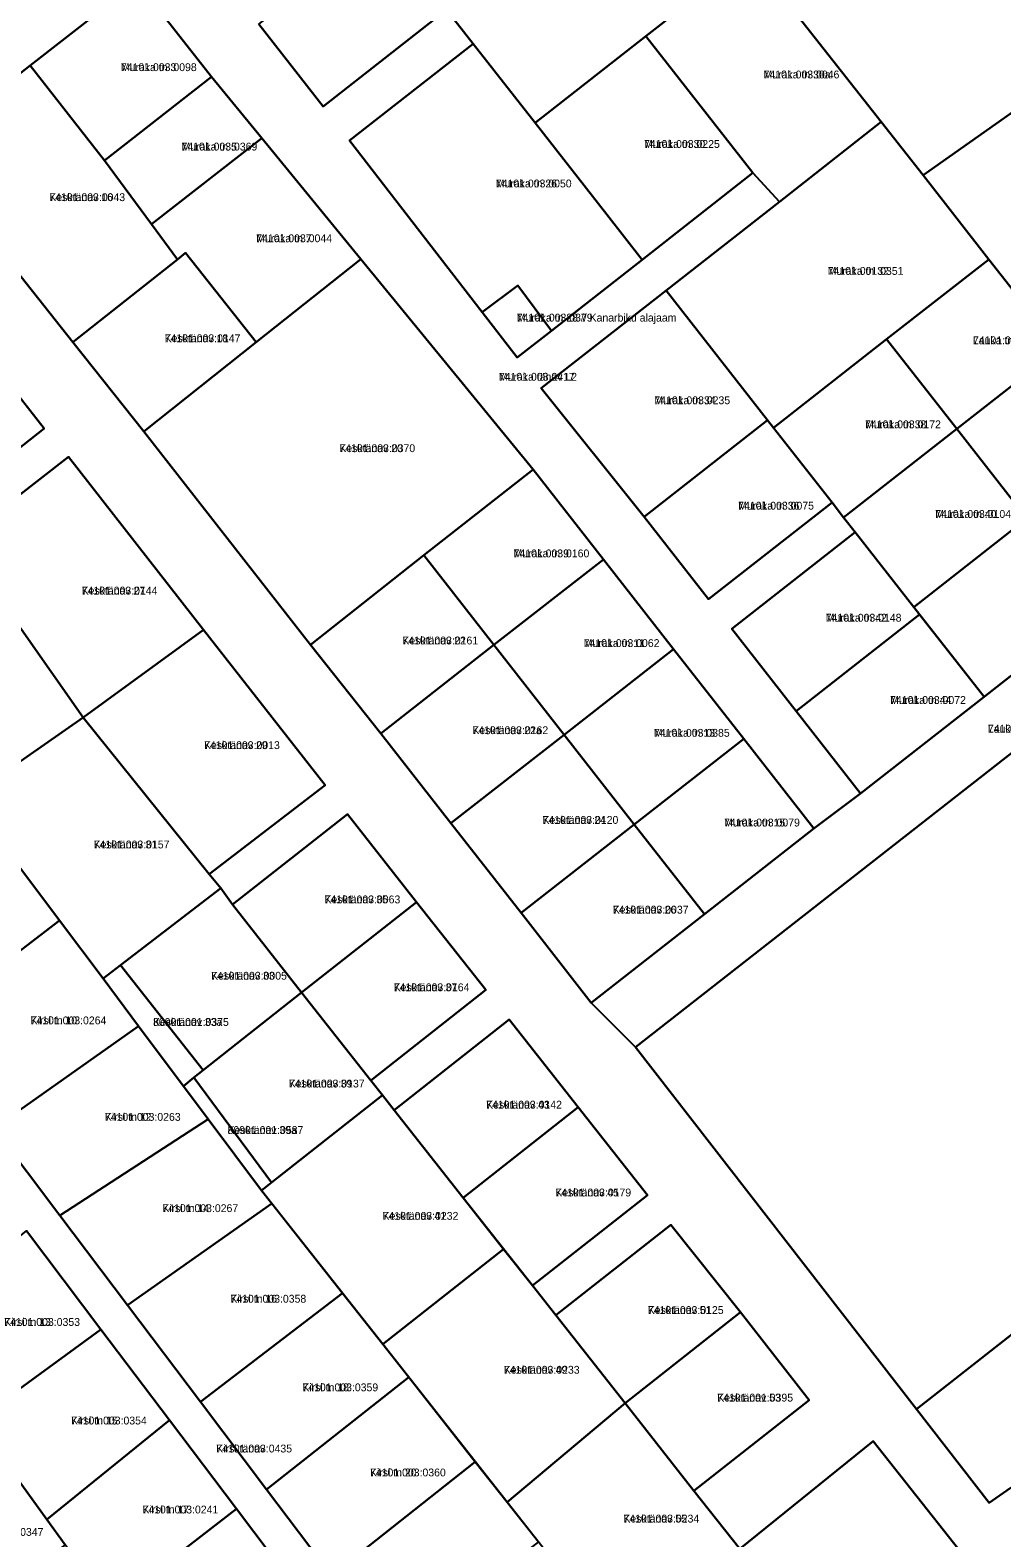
# Model space of a CAD drawing. Extents: x 524000 to 564260, y 6469338 to 6496391.
# Drawn here: x 538966.3 to 539152.2, y 6473209.4 to 6473497.9 of the extents above; entities that cross this region are included whole.
import ezdxf

# ---------------------------------------------------------------- set-up
doc = ezdxf.new("R2010")
doc.units = 0
for name, color, linetype in [('L_AADRESS', 7, 'Continuous'), ('PIIR', 7, 'Continuous'), ('TUNNUS', 7, 'Continuous')]:
    doc.layers.add(name, color=color, linetype=linetype)

msp = doc.modelspace()

# ---------------------------------------------------------------- linework, layer by layer
at = {"layer": 'PIIR'}
for points in [[(538790.44, 6473668.85), (538818.36, 6473633.78), (538821.51, 6473636.25), (538833.78, 6473620.41), (538846.45, 6473604.93), (538843.3, 6473602.49), (538860.15, 6473582.87), (538863.79, 6473577.89), (538881.97, 6473554.41), (538900.33, 6473530.7), (538918.99, 6473507.21), (538937.65, 6473483.72), (538945.42, 6473474.85), (538974.45, 6473438.22), (538987.99, 6473421.14), (539019.92, 6473380.27), (539033.35, 6473363.32), (539046.78, 6473346.15), (539060.21, 6473328.98), (539073.64, 6473311.81), (539082.11, 6473303.28), (539135.86, 6473234.01), (539149.77, 6473216.07), (539153.84, 6473218.89)], [(539010.01, 6473499.08), (539022.34, 6473483.33), (539045.96, 6473501.82), (539051.05, 6473495.32), (539027.39, 6473476.81), (539052.79, 6473443.97), (539059.49, 6473435.32), (539066, 6473440.41), (539083.37, 6473454), (539104.59, 6473470.61), (539109.64, 6473465.11), (539087.98, 6473448.14), (539064.04, 6473429.43), (539083.77, 6473404.8), (539096.1, 6473389.05), (539119.73, 6473407.54), (539121.94, 6473404.7), (539124.16, 6473401.86), (539100.53, 6473383.37), (539112.86, 6473367.62), (539125.19, 6473351.87), (539116.25, 6473345.15), (539102.82, 6473362.32), (539089.39, 6473379.49), (539075.96, 6473396.66), (539062.53, 6473413.83), (539029.57, 6473454.09), (539010.58, 6473477.29), (539000.98, 6473489.02), (538986.76, 6473507.2)], [(538948.47, 6473405.56), (538968.92, 6473421.73), (538954.69, 6473439.8)], [(539151.41, 6473197.77), (539127.62, 6473227.91), (539102.07, 6473207.27), (539093.3, 6473218.4), (539115.36, 6473235.74), (539102.22, 6473252.56), (539088.85, 6473269.31), (539066.83, 6473252.01), (539062.38, 6473257.67), (539084.38, 6473274.99), (539071.14, 6473291.81), (539057.9, 6473308.62), (539035.9, 6473291.27), (539033.67, 6473294.11), (539031.45, 6473296.94), (539053.45, 6473314.26), (539040.21, 6473331.08), (539026.99, 6473347.89), (539004.98, 6473330.58), (539002.72, 6473333.71), (539000.5, 6473336.39), (539022.69, 6473353.47), (538999.46, 6473383.2), (538973.59, 6473416.31), (538952.77, 6473400.07)], [(538959.3, 6473287.82), (538971.92, 6473271.1), (538984.87, 6473253.95), (538998.83, 6473235.46), (539011.51, 6473218.66), (539023.95, 6473202.18)], [(539018.84, 6473197.57), (539005.75, 6473214.93), (538992.9, 6473231.95), (538979.8, 6473249.3), (538965.56, 6473268.15)]]:
    msp.add_lwpolyline(points, dxfattribs=at)
for points in [[(539082.21, 6473592.27), (539089.25, 6473583.53), (539062.91, 6473564.58), (539042.54, 6473549.92), (539021.31, 6473533.32), (538997.68, 6473514.83), (538986.76, 6473507.2), (538966.28, 6473491.18), (538945.42, 6473474.85), (538937.65, 6473483.72), (538977.91, 6473513.5), (538989.08, 6473522.31), (539013.41, 6473539.87), (539012.78, 6473540.65), (539033.15, 6473556.97), (539056.61, 6473573.98), (539079.77, 6473590.52)], [(539144.4, 6473515.04), (539164.83, 6473489.68), (539137.18, 6473470.18), (539129.15, 6473480.37), (539103.98, 6473512.36), (539062.91, 6473564.58), (539089.25, 6473583.53)], [(539103.98, 6473512.36), (539084.1, 6473496.79), (539062.88, 6473480.18), (539051.05, 6473495.32), (539047.35, 6473500.05), (539035.02, 6473515.8), (539056.25, 6473532.4), (539042.54, 6473549.92), (539062.91, 6473564.58)], [(539010.01, 6473499.08), (539033.63, 6473517.57), (539035.02, 6473515.8), (539045.96, 6473501.82), (539022.34, 6473483.33)], [(539129.15, 6473480.37), (539109.64, 6473465.11), (539104.59, 6473470.61), (539084.1, 6473496.79), (539103.98, 6473512.36)], [(538966.28, 6473491.18), (538986.76, 6473507.2), (539000.98, 6473489.02), (538980.5, 6473473)], [(539062.88, 6473480.18), (539084.1, 6473496.79), (539104.59, 6473470.61), (539083.37, 6473454), (539076.59, 6473462.66)], [(539062.88, 6473480.18), (539076.59, 6473462.66), (539083.37, 6473454), (539066, 6473440.41), (539059.59, 6473449.04), (539052.79, 6473443.97), (539027.39, 6473476.81), (539051.05, 6473495.32)], [(538980.5, 6473473), (538989.49, 6473460.78), (538994.43, 6473454.06), (538974.45, 6473438.22), (538945.42, 6473474.85), (538966.28, 6473491.18)], [(539010.58, 6473477.29), (538989.49, 6473460.78), (538980.5, 6473473), (539000.98, 6473489.02)], [(539217.2, 6473423.71), (539190.08, 6473402.58), (539176.64, 6473419.75), (539163.2, 6473436.92), (539149.75, 6473454.02), (539137.18, 6473470.18), (539164.83, 6473489.68)], [(539107.4, 6473423.31), (539087.98, 6473448.14), (539109.64, 6473465.11), (539129.15, 6473480.37), (539137.18, 6473470.18), (539149.75, 6473454.02), (539130.15, 6473438.8), (539108.49, 6473421.85)], [(539029.57, 6473454.09), (539009.54, 6473438.22), (538996, 6473455.3), (538994.43, 6473454.06), (538989.49, 6473460.78), (539010.58, 6473477.29)], [(538974.45, 6473438.22), (538994.43, 6473454.06), (538996, 6473455.3), (539009.54, 6473438.22), (538987.99, 6473421.14)], [(538987.99, 6473421.14), (539009.54, 6473438.22), (539029.57, 6473454.09), (539062.53, 6473413.83), (539041.58, 6473397.44), (539019.92, 6473380.27)], [(539163.2, 6473436.92), (539143.6, 6473421.65), (539130.15, 6473438.8), (539149.75, 6473454.02)], [(539052.79, 6473443.97), (539059.59, 6473449.04), (539066, 6473440.41), (539059.49, 6473435.32)], [(539064.04, 6473429.43), (539087.98, 6473448.14), (539107.4, 6473423.31), (539083.77, 6473404.8)], [(538934.26, 6473423.71), (538954.69, 6473439.8), (538968.92, 6473421.73), (538948.47, 6473405.56)], [(539108.49, 6473421.85), (539130.15, 6473438.8), (539143.6, 6473421.65), (539121.94, 6473404.7), (539119.73, 6473407.54)], [(539176.64, 6473419.75), (539157.03, 6473404.48), (539143.6, 6473421.65), (539163.2, 6473436.92)], [(539217.2, 6473423.71), (539223.86, 6473414.2), (539082.11, 6473303.28), (539073.64, 6473311.81), (539095.3, 6473328.76), (539116.25, 6473345.15), (539125.19, 6473351.87), (539148.81, 6473370.36), (539170.47, 6473387.31), (539190.08, 6473402.58)], [(539083.77, 6473404.8), (539107.4, 6473423.31), (539108.49, 6473421.85), (539119.73, 6473407.54), (539096.1, 6473389.05)], [(539121.94, 6473404.7), (539143.6, 6473421.65), (539157.03, 6473404.48), (539135.37, 6473387.53), (539124.16, 6473401.86)], [(538973.59, 6473416.31), (538999.46, 6473383.2), (538976.38, 6473366.41), (538952.77, 6473400.07)], [(539041.58, 6473397.44), (539062.53, 6473413.83), (539075.96, 6473396.66), (539055.01, 6473380.27)], [(539275.2, 6473343.45), (539180.59, 6473269.14), (539179.11, 6473267.98), (539135.86, 6473234.01), (539082.11, 6473303.28), (539223.86, 6473414.2), (539250.35, 6473373.95)], [(538948.47, 6473405.56), (538952.77, 6473400.07), (538976.38, 6473366.41), (538954.12, 6473350.91), (538951.46, 6473354.55), (538932.72, 6473380.21), (538926.71, 6473388.44)], [(539135.37, 6473387.53), (539157.03, 6473404.48), (539170.47, 6473387.31), (539148.81, 6473370.36)], [(539100.53, 6473383.37), (539124.16, 6473401.86), (539135.37, 6473387.53), (539136.48, 6473386.11), (539112.86, 6473367.62)], [(539019.92, 6473380.27), (539041.58, 6473397.44), (539055.01, 6473380.27), (539033.35, 6473363.32)], [(539055.01, 6473380.27), (539075.96, 6473396.66), (539089.39, 6473379.49), (539068.44, 6473363.1)], [(539112.86, 6473367.62), (539136.48, 6473386.11), (539148.81, 6473370.36), (539125.19, 6473351.87)], [(539022.69, 6473353.47), (539000.5, 6473336.39), (538976.38, 6473366.41), (538999.46, 6473383.2)], [(539033.35, 6473363.32), (539055.01, 6473380.27), (539068.44, 6473363.1), (539046.78, 6473346.15)], [(539089.39, 6473379.49), (539102.82, 6473362.32), (539081.87, 6473345.93), (539068.44, 6473363.1)], [(538976.38, 6473366.41), (539000.5, 6473336.39), (539002.72, 6473333.71), (538983.57, 6473319), (538980.21, 6473316.42), (538971.86, 6473327.53), (538957.3, 6473346.9), (538954.12, 6473350.91)], [(539046.78, 6473346.15), (539068.44, 6473363.1), (539081.87, 6473345.93), (539060.21, 6473328.98)], [(539081.87, 6473345.93), (539102.82, 6473362.32), (539116.25, 6473345.15), (539095.3, 6473328.76)], [(538957.3, 6473346.9), (538971.86, 6473327.53), (538944.9, 6473306.89), (538930.08, 6473326.52)], [(539004.98, 6473330.58), (539026.99, 6473347.89), (539040.21, 6473331.08), (539018.21, 6473313.76)], [(539060.21, 6473328.98), (539081.87, 6473345.93), (539095.3, 6473328.76), (539073.64, 6473311.81)], [(538983.57, 6473319), (539002.72, 6473333.71), (539004.98, 6473330.58), (539018.21, 6473313.76), (538999.35, 6473298.92)], [(539018.21, 6473313.76), (539040.21, 6473331.08), (539053.45, 6473314.26), (539031.45, 6473296.94)], [(538944.9, 6473306.89), (538971.86, 6473327.53), (538980.21, 6473316.42), (538987.02, 6473307.32), (538959.3, 6473287.82)], [(538987.02, 6473307.32), (538980.21, 6473316.42), (538983.57, 6473319), (538999.35, 6473298.92), (538997.58, 6473297.53), (538995.6, 6473295.86)], [(538997.58, 6473297.53), (538999.35, 6473298.92), (539018.21, 6473313.76), (539031.45, 6473296.94), (539033.67, 6473294.11), (539014.81, 6473279.26), (539012.46, 6473277.41)], [(538959.3, 6473287.82), (538987.02, 6473307.32), (539000.34, 6473289.53), (538971.92, 6473271.1)], [(539035.9, 6473291.27), (539057.9, 6473308.62), (539071.14, 6473291.81), (539049.14, 6473274.48)], [(539000.34, 6473289.53), (538995.62, 6473295.83), (538997.58, 6473297.53), (539012.46, 6473277.41), (539010.55, 6473275.89)], [(539033.67, 6473294.11), (539035.9, 6473291.27), (539049.14, 6473274.48), (539056.87, 6473264.66), (539033.73, 6473246.45), (539010.55, 6473275.89), (539014.81, 6473279.26)], [(539062.38, 6473257.67), (539049.14, 6473274.48), (539071.14, 6473291.81), (539084.38, 6473274.99)], [(538971.92, 6473271.1), (539000.34, 6473289.53), (539010.55, 6473275.89), (539012.54, 6473273.36), (538984.87, 6473253.95)], [(539026.04, 6473256.23), (538998.83, 6473235.46), (538984.87, 6473253.95), (539012.54, 6473273.36)], [(539066.83, 6473252.01), (539088.85, 6473269.31), (539102.22, 6473252.56), (539080.1, 6473235.18)], [(539195.05, 6473247.44), (539153.84, 6473218.89), (539149.77, 6473216.07), (539135.86, 6473234.01), (539179.11, 6473267.98), (539180.59, 6473269.14), (539196.73, 6473248.61)], [(538979.8, 6473249.3), (538955.82, 6473231.78), (538944.93, 6473246.86), (538942.92, 6473249.65), (538965.56, 6473268.15)], [(539056.87, 6473264.66), (539062.38, 6473257.67), (539066.83, 6473252.01), (539080.1, 6473235.18), (539057.52, 6473216.25), (539033.73, 6473246.45)], [(539033.73, 6473246.45), (539038.7, 6473240.14), (539011.51, 6473218.66), (538998.83, 6473235.46), (539026.04, 6473256.23)], [(539080.1, 6473235.18), (539102.22, 6473252.56), (539115.36, 6473235.74), (539093.3, 6473218.4)], [(538958.51, 6473228.05), (538955.82, 6473231.78), (538979.8, 6473249.3), (538992.9, 6473231.95), (538969.45, 6473212.9)], [(539051.45, 6473223.95), (539023.95, 6473202.18), (539011.51, 6473218.66), (539038.7, 6473240.14)], [(539093.3, 6473218.4), (539102.07, 6473207.27), (539078.93, 6473189.06), (539057.52, 6473216.25), (539080.1, 6473235.18)], [(538972.93, 6473208.08), (538969.45, 6473212.9), (538992.9, 6473231.95), (539005.75, 6473214.93), (538981.52, 6473196.19)], [(538935.8, 6473211.27), (538958.51, 6473228.05), (538969.45, 6473212.9), (538972.93, 6473208.08), (538950.43, 6473191.51)], [(539101.24, 6473160.73), (539089.19, 6473176.03), (539078.93, 6473189.06), (539102.07, 6473207.27), (539127.62, 6473227.91), (539151.41, 6473197.77), (539102.19, 6473159.52)], [(539023.95, 6473202.18), (539051.45, 6473223.95), (539057.52, 6473216.25), (539063.53, 6473208.62), (539035.51, 6473186.87)], [(539018.84, 6473197.57), (538994.05, 6473178.84), (538986.88, 6473188.76), (538981.52, 6473196.19), (539005.75, 6473214.93)]]:
    msp.add_lwpolyline(points, close=True, dxfattribs=at)

# ---------------------------------------------------------------- texts
at = {"layer": 'L_AADRESS'}
for s, p in [('Muraka tn 3', (538983.63, 6473490.1)), ('Muraka tn 30a', (539106.62, 6473488.7)), ('Muraka tn 5', (538995.23, 6473474.9)), ('Muraka tn 30', (539083.74, 6473475.4)), ('Muraka tn 26', (539055.38, 6473467.84)), ('Kesktänav 16', (538969.93, 6473465.22)), ('Muraka tn 7', (539009.53, 6473457.35)), ('Muraka tn 32', (539118.89, 6473451.11)), ('Muraka tn 28 // Kanarbiku alajaam', (539059.39, 6473442.17)), ('Kesktänav 18', (538992, 6473438.22)), ('Lauka tn 8', (539146.69, 6473437.83)), ('Muraka tänav L2', (539055.97, 6473430.85)), ('Muraka tn 34', (539085.72, 6473426.35)), ('Muraka tn 38', (539126.05, 6473421.75)), ('Kesktänav 20', (539025.44, 6473417.18)), ('Muraka tn 36', (539101.76, 6473406.18)), ('Muraka tn 40', (539139.48, 6473404.59)), ('Muraka tn 9', (539058.77, 6473397.05)), ('Kesktänav 27', (538976.12, 6473389.93)), ('Muraka tn 42', (539118.51, 6473384.74)), ('Kesktänav 22', (539037.49, 6473380.38)), ('Muraka tn 11', (539072.2, 6473379.88)), ('Muraka tn 44', (539130.84, 6473368.99)), ('Kesktänav 22a', (539050.9, 6473363.21)), ('Muraka tn 13', (539085.63, 6473362.71)), ('Lauka tänav', (539149.55, 6473363.5)), ('Kesktänav 29', (538999.54, 6473360.35)), ('Kesktänav 24', (539064.32, 6473346.04)), ('Muraka tn 15', (539099.06, 6473345.54)), ('Kesktänav 31', (538978.42, 6473341.34)), ('Kesktänav 35', (539022.59, 6473330.83)), ('Kesktänav 26', (539077.76, 6473328.87)), ('Kesktänav 33', (539000.89, 6473316.22)), ('Kesktänav 37', (539035.83, 6473314.01)), ('Kirsi tn 10', (538966.34, 6473307.68)), ('Kesktänav 33a', (538989.78, 6473307.37)), ('Kesktänav 39', (539015.77, 6473295.59)), ('Kesktänav 43', (539053.53, 6473291.55)), ('Kirsi tn 12', (538980.56, 6473289.21)), ('Kesktänav 39a', (539004.04, 6473286.69)), ('Kesktänav 45', (539066.77, 6473274.74)), ('Kirsi tn 14', (538991.57, 6473271.74)), ('Kesktänav 41', (539033.71, 6473270.27)), ('Kirsi tn 16', (539004.59, 6473254.41)), ('Kirsi tn 13', (538961.3, 6473249.96)), ('Kesktänav 51', (539084.47, 6473252.24)), ('Kesktänav 49', (539056.91, 6473240.81)), ('Kirsi tn 18', (539018.36, 6473237.45)), ('Kesktänav 53', (539097.76, 6473235.48)), ('Kirsi tn 15', (538974.08, 6473231.1)), ('Kirsi tänav', (539001.88, 6473225.74)), ('Kirsi tn 20', (539031.3, 6473221.16)), ('Kirsi tn 17', (538987.76, 6473214.07)), ('Kesktänav 55', (539079.8, 6473212.33))]:
    msp.add_text(s, height=1.5, dxfattribs=at).set_placement(p)
at = {"layer": 'TUNNUS'}
for s, p in [('74101:003:0098', (538983.63, 6473490.1)), ('74101:003:0046', (539106.62, 6473488.7)), ('74101:003:0369', (538995.23, 6473474.9)), ('74101:003:0225', (539083.74, 6473475.4)), ('74101:003:0050', (539055.38, 6473467.84)), ('74101:003:0043', (538969.93, 6473465.22)), ('74101:003:0044', (539009.53, 6473457.35)), ('74101:001:0351', (539118.89, 6473451.11)), ('74101:003:0379', (539059.39, 6473442.17)), ('74101:003:0147', (538992, 6473438.22)), ('74101:003:0039', (539146.69, 6473437.83)), ('74101:003:0417', (539055.97, 6473430.85)), ('74101:003:0235', (539085.72, 6473426.35)), ('74101:003:0172', (539126.05, 6473421.75)), ('74101:003:0370', (539025.44, 6473417.18)), ('74101:003:0075', (539101.76, 6473406.18)), ('74101:003:0104', (539139.48, 6473404.59)), ('74101:003:0160', (539058.77, 6473397.05)), ('74101:003:0144', (538976.12, 6473389.93)), ('74101:003:0148', (539118.51, 6473384.74)), ('74101:003:0161', (539037.49, 6473380.38)), ('74101:003:0062', (539072.2, 6473379.88)), ('74101:003:0072', (539130.84, 6473368.99)), ('74101:003:0162', (539050.9, 6473363.21)), ('74101:003:0385', (539085.63, 6473362.71)), ('74101:003:0431', (539149.55, 6473363.5)), ('74101:003:0013', (538999.54, 6473360.35)), ('74101:003:0120', (539064.32, 6473346.04)), ('74101:003:0079', (539099.06, 6473345.54)), ('74101:003:0157', (538978.42, 6473341.34)), ('74101:003:0063', (539022.59, 6473330.83)), ('74101:003:0037', (539077.76, 6473328.87)), ('74101:003:0005', (539000.89, 6473316.22)), ('74101:003:0164', (539035.83, 6473314.01)), ('74101:003:0264', (538966.34, 6473307.68)), ('80901:001:0375', (538989.78, 6473307.37)), ('74101:003:0137', (539015.77, 6473295.59)), ('74101:003:0142', (539053.53, 6473291.55)), ('74101:003:0263', (538980.56, 6473289.21)), ('80901:001:0587', (539004.04, 6473286.69)), ('74101:003:0179', (539066.77, 6473274.74)), ('74101:003:0267', (538991.57, 6473271.74)), ('74101:003:0232', (539033.71, 6473270.27)), ('74101:003:0358', (539004.59, 6473254.41)), ('74101:003:0353', (538961.3, 6473249.96)), ('74101:003:0125', (539084.47, 6473252.24)), ('74101:003:0233', (539056.91, 6473240.81)), ('74101:003:0359', (539018.36, 6473237.45)), ('74101:001:0395', (539097.76, 6473235.48)), ('74101:003:0354', (538974.08, 6473231.1)), ('74101:003:0435', (539001.88, 6473225.74)), ('74101:003:0360', (539031.3, 6473221.16)), ('74101:003:0241', (538987.76, 6473214.07)), ('74101:003:0234', (539079.8, 6473212.33)), ('74101:003:0347', (538954.3, 6473209.78))]:
    msp.add_text(s, height=1.5, dxfattribs=at).set_placement(p)

doc.saveas('drawing.dxf')
